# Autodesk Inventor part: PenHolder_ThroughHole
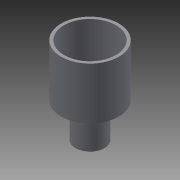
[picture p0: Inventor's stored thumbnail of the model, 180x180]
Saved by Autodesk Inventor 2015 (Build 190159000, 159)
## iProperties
Created: 2017-05
Part Number: PenHolder_ThroughHole
Material: Generisch
Document SubType Name: Modeling
Designer: Andreas
Density: 1 g/cm^3
Appearance: Vorgabe
Author: Andreas
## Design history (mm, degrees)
sketch "Skizze1"
  geometry: C1 r 50 at (0, 0); 1 further point
  constraints: 1 centre point, 1 coincident
  dimensions: "d0" = 100 diameter of C1
extrude "Extrusion1" new body sketch "Skizze1" distance "d1" = 90; taper "d2" = 0 deg
sketch "Skizze2"
  geometry: C1 r 45 at (0, 0); 1 further point
  constraints: 1 centre point, 1 coincident
  dimensions: "d3" = 90 diameter of C1
extrude "Extrusion2" cut sketch "Skizze2" distance "d4" = 85; taper "d5" = 0 deg
sketch "Skizze3"
  geometry: C1 r 25 at (0, 0); 1 further point
  constraints: 1 centre point, 1 coincident
  dimensions: "d6" = 50 diameter of C1
extrude "Extrusion3" join sketch "Skizze3" distance "d7" = 60; taper "d8" = 0 deg
node "Volumenkörper1"
